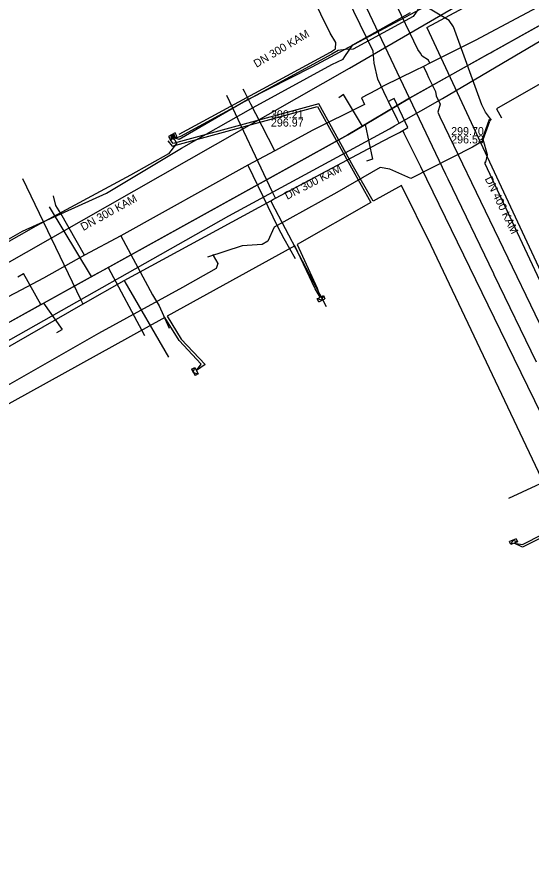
# Model space of a CAD drawing. Extents: x -600391 to -599491, y -1160176 to -1159402.
# Drawn here: x -600196.8 to -600145.4, y -1159907.9 to -1159823.2 of the extents above; entities that cross this region are included whole.
import ezdxf

# ---------------------------------------------------------------- set-up
doc = ezdxf.new("R2010")
doc.units = 0
for name, color, linetype in [('28', 7, 'Continuous'), ('31', 7, 'Continuous'), ('CETIN_linie', 7, 'Continuous'), ('Vrstva 1', 7, 'Continuous'), ('Vrstva 12', 7, 'Continuous'), ('Vrstva 13', 7, 'Continuous'), ('Vrstva 19', 7, 'Continuous'), ('Vrstva 42', 7, 'Continuous'), ('Vrstva 43', 7, 'Continuous'), ('Vrstva 44', 7, 'Continuous'), ('Vrstva 55', 7, 'Continuous'), ('Vrstva 58', 7, 'Continuous'), ('Vrstva 9', 7, 'Continuous')]:
    doc.layers.add(name, color=color, linetype=linetype)

# ---------------------------------------------------------------- blocks, each defined once
blk = doc.blocks.new('NN630')
at = {"layer": '31'}
for points in [[(0, -0.7), (-0.7, 0)], [(-0.7, -0.7), (-0.7, 0), (0.7, 0), (0.7, -0.7)], [(-0.7, -0.7), (0.7, -0.7)], [(0, -0.7), (0.7, 0)]]:
    blk.add_lwpolyline(points, dxfattribs=at)
blk = doc.blocks.new('NN620')
at = {"layer": '28'}
for points in [[(0.75, 0), (-0.75, 0)], [(-0.75, 0), (-0.75, -0.75)], [(0.75, -0.75), (0.75, 0)], [(-0.75, -0.75), (0.75, -0.75)], [(0.37, -0.18), (-0.38, -0.18)], [(-0.38, -0.18), (-0.38, -0.56)], [(-0.38, -0.56), (0.37, -0.56)], [(0.32, -0.23), (-0.33, -0.23)], [(-0.33, -0.23), (-0.33, -0.51)], [(-0.33, -0.51), (0.32, -0.51)], [(0.27, -0.27), (-0.28, -0.27)], [(-0.28, -0.27), (-0.28, -0.46)], [(-0.28, -0.46), (0.27, -0.46)], [(0.23, -0.32), (-0.23, -0.32)], [(-0.23, -0.32), (-0.23, -0.42)], [(-0.23, -0.42), (0.23, -0.42)], [(-0.19, -0.37), (0.19, -0.37)], [(0.23, -0.42), (0.23, -0.32)], [(0.27, -0.46), (0.27, -0.27)], [(0.32, -0.51), (0.32, -0.23)], [(0.37, -0.56), (0.37, -0.18)]]:
    blk.add_lwpolyline(points, dxfattribs=at)

msp = doc.modelspace()

# ---------------------------------------------------------------- linework, layer by layer
at = {"layer": 'CETIN_linie'}
for points in [[(-600155.82, -1159824.25), (-600096.42, -1159792.4), (-600032.25, -1159754.89)], [(-600155.82, -1159824.25), (-600131.59, -1159876.14), (-600105.43, -1159931.66), (-600079.78, -1159985.02), (-600054.68, -1160038.07), (-600031.21, -1160088.32), (-600065.96, -1160109.81), (-600092.69, -1160126.24), (-600115.43, -1160139.89), (-600155.2, -1160162.97), (-600165.23, -1160150.94)]]:
    msp.add_lwpolyline(points, dxfattribs=at)
at = {"layer": 'Vrstva 1'}
for points in [[(-600127.04, -1159814.25), (-600157.56, -1159831.33)], [(-600164.153, -1159830.958), (-600164.626, -1159831.287)], [(-600162.264, -1159834.13), (-600164.153, -1159830.958)], [(-600157.56, -1159831.33), (-600163.71, -1159834.99)], [(-600161.988, -1159833.965), (-600161.262, -1159837.429)], [(-600163.71, -1159834.99), (-600200.98, -1159855.6)], [(-600161.262, -1159837.429), (-600161.852, -1159837.622)], [(-600189.351, -1159849.169), (-600193.552, -1159842.186)], [(-600187.688, -1159848.25), (-600184.068, -1159855.062)], [(-600196.75, -1159849.19), (-600196.18, -1159848.86)], [(-600194.426, -1159851.976), (-600196.18, -1159848.86)], [(-600194.164, -1159851.831), (-600192.291, -1159854.451)], [(-600192.851, -1159854.771), (-600192.291, -1159854.451)]]:
    msp.add_lwpolyline(points, dxfattribs=at)
at = {"layer": 'Vrstva 13'}
for p, q in [((-600159.65, -1159831.68), (-600159.82, -1159831.318)), ((-600159.337, -1159831.51), (-600159.65, -1159831.68)), ((-600158.74, -1159833.51), (-600159.65, -1159831.68)), ((-600159.03, -1159834.09), (-600158.572, -1159833.828)), ((-600158.572, -1159833.828), (-600158.74, -1159833.51)), ((-600158.559, -1159834.76), (-600158.208, -1159834.567)), ((-600158.068, -1159834.849), (-600158.208, -1159834.567))]:
    msp.add_line(p, q, dxfattribs=at)
for points in [[(-600161.18, -1159826.62), (-600168.95, -1159810.66), (-600176.39, -1159794.77), (-600178.7, -1159789.98), (-600183.86, -1159779.17), (-600184.83, -1159777.12), (-600190.37, -1159765.45), (-600191.37, -1159763.33), (-600196.96, -1159751.61), (-600199.19, -1159746.92), (-600201.13, -1159742.84), (-600201.62, -1159741.81), (-600205.05, -1159734.61), (-600208.57, -1159727.22), (-600210.91, -1159722.31), (-600212.83, -1159718.29), (-600213.07, -1159717.78), (-600218.37, -1159706.66), (-600223.5, -1159695.91), (-600225.68, -1159691.33), (-600227.32, -1159687.89), (-600233.15, -1159675.83), (-600235.99, -1159670.03)], [(-600158.572, -1159833.828), (-600154.25, -1159831.35), (-600135.851, -1159820.513), (-600116.135, -1159809.613), (-600100.05, -1159800.72), (-600081.768, -1159790.54), (-600067.006, -1159782.231), (-600066.237, -1159781.786)], [(-600159.82, -1159831.318), (-600160.71, -1159829.42), (-600161.07, -1159827.82), (-600161.18, -1159826.62)], [(-600373.54, -1159891.359), (-600372.925, -1159890.911), (-600370.89, -1159889.39), (-600366.85, -1159887.18), (-600352.305, -1159879.13), (-600335.078, -1159869.594), (-600317.345, -1159859.78), (-600300.082, -1159850.224), (-600283.27, -1159840.919), (-600267.84, -1159832.38), (-600263.95, -1159830.23), (-600262.43, -1159830.62), (-600255.08, -1159843.6), (-600247.73, -1159856.58), (-600236, -1159876.75), (-600235.14, -1159876.86), (-600231.99, -1159875.01), (-600217.638, -1159866.818), (-600199.226, -1159856.435), (-600175.635, -1159843.102), (-600159.56, -1159834.39), (-600159.03, -1159834.09)], [(-600170.949, -1159841.328), (-600171.009, -1159841.2), (-600171.241, -1159840.717), (-600175.84, -1159831.08)], [(-600158.208, -1159834.567), (-600157.711, -1159834.274), (-600159.08, -1159831.37), (-600159.337, -1159831.51)], [(-600235.729, -1159878.08), (-600234.8, -1159877.56), (-600231.39, -1159875.51), (-600220.063, -1159869.02), (-600206.009, -1159860.966), (-600190.21, -1159851.914), (-600186.095, -1159849.564), (-600171.436, -1159841.59), (-600171.14, -1159841.43), (-600170.949, -1159841.328), (-600160.18, -1159835.6), (-600159.206, -1159835.095), (-600158.559, -1159834.76)], [(-600080.79, -1159998.87), (-600081.22, -1159997.9), (-600084.083, -1159991.85), (-600086.711, -1159986.328), (-600092.25, -1159974.69), (-600092.875, -1159973.303), (-600095.81, -1159966.83), (-600099.22, -1159959.42), (-600104.56, -1159947.82), (-600110.84, -1159933.71), (-600113.13, -1159928.57), (-600117.44, -1159919.3), (-600122.36, -1159908.74), (-600128.42, -1159895.95), (-600135.15, -1159882.07), (-600141.58, -1159868.63), (-600148.44, -1159854.56), (-600156.4, -1159838.21), (-600158.068, -1159834.849)], [(-600190.21, -1159851.914), (-600190.262, -1159851.807), (-600190.425, -1159851.462), (-600196.222, -1159839.383)], [(-600171.436, -1159841.59), (-600171.351, -1159841.749), (-600165.892, -1159852.162)], [(-600186.095, -1159849.564), (-600186.025, -1159849.687), (-600181.661, -1159857.24)], [(-600141.58, -1159868.63), (-600141.74, -1159868.63), (-600147.638, -1159871.375)]]:
    msp.add_lwpolyline(points, dxfattribs=at)
at = {"layer": 'Vrstva 19'}
for points in [[(-600141.71, -1159820.61), (-600150.98, -1159825.58), (-600155.51, -1159827.83), (-600156.15, -1159828.15), (-600156.98, -1159828.56), (-600160.11, -1159830.11), (-600160.89, -1159830.519), (-600162.36, -1159831.29)], [(-600155.51, -1159827.83), (-600155.66, -1159827.54), (-600156.28, -1159827.12), (-600156.44, -1159826.82), (-600156.71, -1159826.45), (-600159.16, -1159821.35), (-600159.52, -1159820.6), (-600159.65, -1159820.33)], [(-600156.15, -1159828.15), (-600155.8, -1159828.85), (-600155.63, -1159829.28), (-600155.43, -1159829.67), (-600154.93, -1159830.67)], [(-600171.017, -1159836.583), (-600172.907, -1159832.901), (-600173.41, -1159831.92), (-600174.049, -1159830.675), (-600174.18, -1159830.42)], [(-600162.36, -1159831.29), (-600162.05, -1159831.96), (-600162.73, -1159832.29), (-600166.82, -1159834.34), (-600167.21, -1159834.52), (-600171.017, -1159836.583), (-600173.707, -1159838.041), (-600186.446, -1159845.082), (-600190.06, -1159847.04), (-600194.17, -1159849.32), (-600196.99, -1159850.84), (-600197.26, -1159850.98), (-600200.83, -1159852.89), (-600203.64, -1159854.43), (-600203.9, -1159854.57), (-600207.12, -1159856.33), (-600208.202, -1159856.922), (-600214.11, -1159860.15), (-600224.77, -1159865.97), (-600231.3, -1159869.53), (-600235.81, -1159871.96)], [(-600154.93, -1159830.67), (-600154.88, -1159831.11), (-600154.48, -1159831.94), (-600154.7, -1159832.72), (-600154.52, -1159833.2), (-600138.21, -1159867)], [(-600173.707, -1159838.041), (-600170.73, -1159844.24), (-600170.11, -1159845.36), (-600168.97, -1159847.35)], [(-600190.06, -1159847.04), (-600192.449, -1159842.88), (-600192.92, -1159842.06), (-600193.17, -1159841.09)], [(-600186.446, -1159845.082), (-600183.27, -1159851), (-600182.61, -1159852.11), (-600181.6, -1159854.33)]]:
    msp.add_lwpolyline(points, dxfattribs=at)
at = {"layer": 'Vrstva 42'}
for points in [[(-600180.579, -1159834.928), (-600165.447, -1159826.718), (-600164.935, -1159826.413), (-600164.916, -1159825.758), (-600165.473, -1159824.843), (-600169.234, -1159817.191), (-600175.425, -1159803.663), (-600180.98, -1159792.277), (-600181.316, -1159792.456), (-600181.239, -1159791.715), (-600182.323, -1159789.206), (-600185.289, -1159783.095), (-600185.72, -1159782.948), (-600189.244, -1159784.694), (-600190.099, -1159785.056), (-600189.375, -1159784.486), (-600185.738, -1159782.678), (-600185.62, -1159782.525), (-600190.145, -1159772.909)], [(-600177.948, -1159775.133), (-600176.423, -1159780.074), (-600176.429, -1159780.729), (-600175.904, -1159781.319), (-600170.151, -1159792.744), (-600169.449, -1159792.605), (-600168.696, -1159792.712), (-600169.507, -1159792.871), (-600170.005, -1159792.97), (-600170.221, -1159793.274), (-600163.747, -1159806.642), (-600163.625, -1159807.284), (-600162.988, -1159808.178), (-600159.624, -1159815.215), (-600156.653, -1159821.453), (-600156.698, -1159822.492), (-600157.172, -1159823.173), (-600163.167, -1159826.433), (-600163.953, -1159826.461), (-600164.689, -1159826.558), (-600165.323, -1159826.935), (-600180.454, -1159835.177), (-600180.955, -1159835.33), (-600181.078, -1159835.24)], [(-600140.79, -1159813.9), (-600152.87, -1159820.51), (-600163.16, -1159825.99), (-600167.31, -1159828.23), (-600173.76, -1159831.51), (-600180.6, -1159835.48), (-600181.14, -1159835.31)], [(-600181.732, -1159835.603), (-600181.308, -1159836.132), (-600166.76, -1159832.161), (-600163.351, -1159838.305), (-600161.401, -1159841.771), (-600168.791, -1159845.966), (-600166.771, -1159850.319), (-600166.475, -1159851.229), (-600167.001, -1159850.385), (-600169.01, -1159846.087), (-600181.806, -1159853.142), (-600180.378, -1159855.417), (-600178, -1159857.972), (-600178.872, -1159858.58), (-600178.385, -1159857.926), (-600180.577, -1159855.57), (-600182.026, -1159853.261), (-600202.389, -1159864.484), (-600229.355, -1159879.519), (-600229.511, -1159879.87), (-600216.116, -1159904.114), (-600205.42, -1159898.474)], [(-600142.063, -1159874.132), (-600146.23, -1159876.245), (-600147.073, -1159875.843), (-600146.227, -1159875.963), (-600142.177, -1159873.91), (-600155.379, -1159846.06), (-600158.346, -1159840.055), (-600161.185, -1159841.645), (-600163.133, -1159838.183), (-600166.611, -1159831.897), (-600181.188, -1159835.863), (-600181.493, -1159835.461)], [(-600181.231, -1159835.327), (-600181.043, -1159835.507), (-600180.86, -1159835.88), (-600181.65, -1159836.9), (-600185.45, -1159839.02), (-600194.93, -1159844.14), (-600201.55, -1159847.87), (-600203.1, -1159848.62), (-600204.38, -1159848.18), (-600204.747, -1159847.227), (-600204.757, -1159847.072)]]:
    msp.add_lwpolyline(points, dxfattribs=at)
at = {"layer": 'Vrstva 44'}
msp.add_lwpolyline([(-600224.31, -1159913.83), (-600229.51, -1159904.42), (-600234.53, -1159895.46), (-600239.1, -1159886.99), (-600243.11, -1159879.66), (-600246.67, -1159873.36), (-600246.84, -1159872.99), (-600246.7, -1159872.66), (-600246.37, -1159872.32), (-600245.12, -1159871.59), (-600238.49, -1159868.07), (-600233.22, -1159865.15), (-600226.64, -1159861.55), (-600216.98, -1159856.16), (-600207.52, -1159851.02), (-600196.27, -1159844.63), (-600187.87, -1159840.83), (-600180.35, -1159836.34), (-600173.18, -1159832.26), (-600165.31, -1159827.98), (-600164.17, -1159827.44), (-600164.02, -1159827.18), (-600163.23, -1159825.99), (-600157.45, -1159822.77)], dxfattribs=at)
at = {"layer": 'Vrstva 55'}
for points in [[(-600149.351, -1159833.541), (-600149.95, -1159832.72), (-600150.3, -1159832.01), (-600153.14, -1159824.2), (-600153.57, -1159823.58), (-600156.38, -1159821.89), (-600157.19, -1159821.09), (-600163.91, -1159806.66), (-600169.65, -1159794.38), (-600176.01, -1159781.35), (-600182.61, -1159767.26)], [(-600070.348, -1159787.623), (-600070.42, -1159787.69), (-600071.48, -1159789.07), (-600078.39, -1159793.19), (-600080.55, -1159794.15), (-600087.34, -1159797.87), (-600097.688, -1159803.79), (-600098.116, -1159803.094), (-600098.24, -1159802.93), (-600098.224, -1159803.146), (-600097.792, -1159803.85), (-600108.81, -1159810.18), (-600119.01, -1159815.94), (-600125.457, -1159819.362), (-600125.883, -1159818.53), (-600125.96, -1159818.45), (-600125.997, -1159818.57), (-600125.562, -1159819.419), (-600136.32, -1159825.44), (-600144.71, -1159830.04), (-600148.85, -1159832.39), (-600148.339, -1159833.297)], [(-600149.453, -1159833.605), (-600149.564, -1159833.453), (-600150.286, -1159835.445), (-600150.238, -1159835.618), (-600151.25, -1159836.23), (-600157.42, -1159839.35), (-600159.52, -1159838.44), (-600160.47, -1159838.26), (-600164.83, -1159840.75), (-600171.08, -1159844.22), (-600171.73, -1159845.63), (-600172.29, -1159845.98), (-600174.3, -1159846.1), (-600177.76, -1159847.23)], [(-600143.01, -1159852.76), (-600149.96, -1159837.89), (-600149.98, -1159837.71), (-600149.924, -1159837.747), (-600149.73, -1159836.99), (-600150.16, -1159835.45), (-600149.503, -1159833.636)], [(-600177.26, -1159846.95), (-600177.2, -1159847.08), (-600176.71, -1159847.87), (-600176.88, -1159848.38), (-600180.27, -1159850.28), (-600188.66, -1159854.85), (-600198.23, -1159860.34), (-600204.737, -1159863.881), (-600205.289, -1159863.141), (-600206.287, -1159863.1), (-600206.46, -1159863.15), (-600206.293, -1159863.22), (-600205.351, -1159863.259), (-600204.843, -1159863.94), (-600211.6, -1159867.76), (-600219.34, -1159872.1), (-600227.51, -1159876.52)]]:
    msp.add_lwpolyline(points, dxfattribs=at)
at = {"layer": 'Vrstva 58'}
msp.add_lwpolyline([(-600220.159, -1159921.243), (-600245.973, -1159874.147), (-600235.595, -1159868.362), (-600209.303, -1159854.361), (-600163.546, -1159828.331), (-600142.156, -1159815.889)], dxfattribs=at)
at = {"layer": 'Vrstva 9'}
for points in [[(-600157.533, -1159831.325), (-600167.65, -1159809.99), (-600167.763, -1159809.751), (-600169.238, -1159806.621), (-600169.46, -1159806.15), (-600171.83, -1159801.11)], [(-600157.533, -1159831.325), (-600149.695, -1159826.942), (-600149.442, -1159826.8), (-600149.093, -1159826.605), (-600148.831, -1159826.459), (-600127.04, -1159814.25)], [(-600163.71, -1159834.99), (-600162.264, -1159834.13), (-600162.195, -1159834.089), (-600161.988, -1159833.965), (-600157.533, -1159831.325)], [(-600144.85, -1159857.74), (-600149.07, -1159848.99), (-600149.12, -1159848.886), (-600153.68, -1159839.44), (-600153.908, -1159838.96), (-600157.533, -1159831.325)], [(-600200.98, -1159855.6), (-600194.426, -1159851.976), (-600194.308, -1159851.911), (-600194.164, -1159851.831), (-600193.88, -1159851.674), (-600189.351, -1159849.169), (-600189.06, -1159849.008), (-600187.688, -1159848.25), (-600187.401, -1159848.091), (-600163.71, -1159834.99)]]:
    msp.add_lwpolyline(points, dxfattribs=at)

# ---------------------------------------------------------------- block references
at = {"layer": 'Vrstva 43'}
for name, p, xscale, yscale, rotation in [('NN620', (-600181.14, -1159835.31), 0.5000000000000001, 0.4999999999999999, -151), ('NN630', (-600166.474, -1159851.229), 0.5, 0.5, 26.999999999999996), ('NN630', (-600178.872, -1159858.58), 0.5, 0.5, -61.000000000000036), ('NN630', (-600147.073, -1159875.843), 0.5, 0.5000000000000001, -158.00000000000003)]:
    msp.add_blockref(name, p, dxfattribs=dict(at, xscale=xscale, yscale=yscale, rotation=rotation))

# ---------------------------------------------------------------- texts
at = {"layer": 'Vrstva 12'}
for s, rotation, p in [('DN 300 KAM', 30.74182, (-600172.853, -1159828.309)), ('DN 300 KAM', 27.44468, (-600169.783, -1159841.502)), ('DN 400 KAM', 295.76081, (-600150.031, -1159839.385)), ('DN 300 KAM', 28.93437, (-600190.185, -1159844.623))]:
    msp.add_text(s, height=0.8, rotation=rotation, dxfattribs=at).set_placement(p)
for s, p in [('300.21', (-600171.411, -1159833.342)), ('296.97', (-600171.411, -1159834.174)), ('299.70', (-600153.377, -1159835.024)), ('296.53', (-600153.377, -1159835.856))]:
    msp.add_text(s, height=0.8, dxfattribs=at).set_placement(p)

doc.saveas('drawing.dxf')
